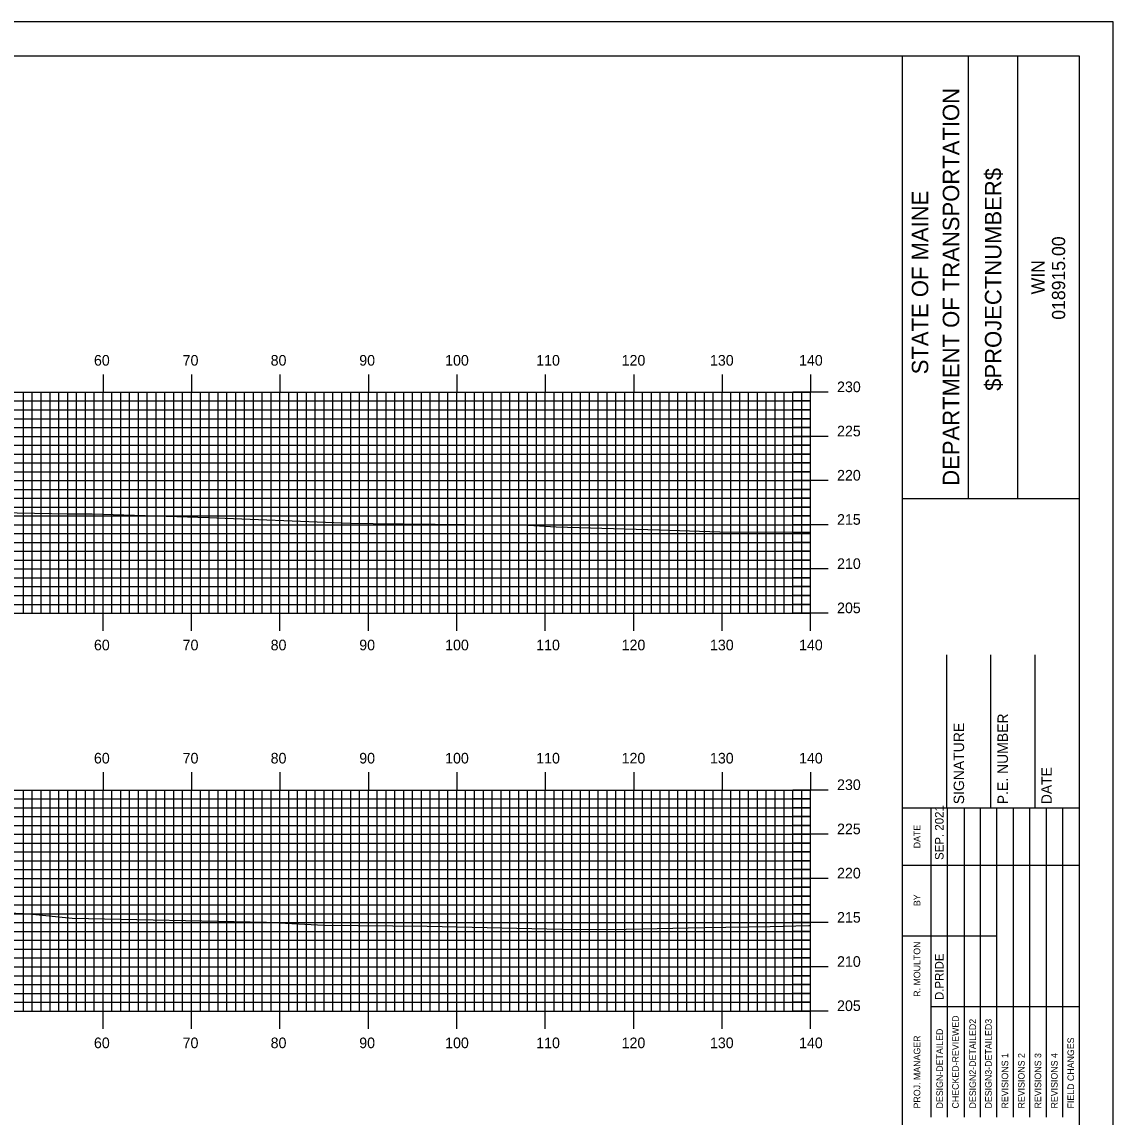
# Model space of a CAD drawing. Extents: x 1819637 to 1819981, y 442591 to 442811.
# Drawn here: x 1819854 to 1819977.4, y 442686.7 to 442810.5 of the extents above; entities that cross this region are included whole.
import ezdxf

# ---------------------------------------------------------------- set-up
doc = ezdxf.new("R2010")
doc.units = 0
for name, color, linetype in [('BORDER', 7, 'Continuous'), ('H_V ANNOTATION', 7, 'Continuous'), ('MAJOR', 7, 'Continuous'), ('MINOR', 7, 'Continuous'), ('PLOT BOUNDARY', 7, 'Continuous'), ('S_Roadway_Centerline', 7, 'Continuous')]:
    doc.layers.add(name, color=color, linetype=linetype)

msp = doc.modelspace()

# ---------------------------------------------------------------- linework, layer by layer
at = {"layer": 'BORDER'}
for p, q in [((1819953.58, 442596.67), (1819953.58, 442806.67)), ((1819961.03, 442756.66), (1819961.03, 442806.66)), ((1819966.62, 442756.66), (1819966.62, 442806.66)), ((1819953.58, 442756.65), (1819973.58, 442756.65)), ((1819958.58, 442721.67), (1819958.58, 442738.97)), ((1819963.58, 442721.67), (1819963.58, 442738.97)), ((1819968.58, 442721.67), (1819968.58, 442738.97)), ((1819953.58, 442721.67), (1819973.58, 442721.67))]:
    msp.add_line(p, q, dxfattribs=at)
msp.add_lwpolyline([(1819653.58, 442596.67), (1819973.58, 442596.67), (1819973.58, 442806.67), (1819653.58, 442806.67)], close=True, dxfattribs=at)
for points in [[(1819956.81, 442715.17), (1819956.81, 442721.67)], [(1819958.67, 442686.68), (1819958.67, 442721.67)], [(1819960.54, 442721.67), (1819960.54, 442686.68)], [(1819962.4, 442686.68), (1819962.4, 442721.67)], [(1819964.26, 442686.68), (1819964.26, 442721.67)], [(1819966.13, 442686.68), (1819966.13, 442721.67)], [(1819967.99, 442686.68), (1819967.99, 442721.67)], [(1819969.85, 442686.68), (1819969.85, 442721.67)], [(1819971.72, 442686.68), (1819971.72, 442721.67)], [(1819956.81, 442686.68), (1819956.81, 442720.26)], [(1819953.58, 442715.17), (1819973.58, 442715.17)], [(1819953.58, 442707.17), (1819956.81, 442707.17)], [(1819956.81, 442707.17), (1819964.26, 442707.17)], [(1819956.81, 442699.17), (1819973.58, 442699.17)]]:
    msp.add_lwpolyline(points, dxfattribs=at)
at = {"layer": 'MAJOR'}
for p, q in [((1819863.18, 442770.67), (1819863.18, 442768.67)), ((1819873.18, 442770.67), (1819873.18, 442768.67)), ((1819883.18, 442770.67), (1819883.18, 442768.67)), ((1819893.18, 442770.67), (1819893.18, 442768.67)), ((1819903.18, 442770.67), (1819903.18, 442768.67)), ((1819913.18, 442770.67), (1819913.18, 442768.67)), ((1819923.18, 442770.67), (1819923.18, 442768.67)), ((1819933.18, 442770.67), (1819933.18, 442768.67)), ((1819943.18, 442770.67), (1819943.18, 442768.67)), ((1819663.18, 442768.67), (1819943.18, 442768.67)), ((1819663.18, 442768.67), (1819943.18, 442768.67)), ((1819863.18, 442743.67), (1819863.18, 442768.67)), ((1819873.18, 442743.67), (1819873.18, 442768.67)), ((1819883.18, 442743.67), (1819883.18, 442768.67)), ((1819893.18, 442743.67), (1819893.18, 442768.67)), ((1819903.18, 442743.67), (1819903.18, 442768.67)), ((1819913.18, 442743.67), (1819913.18, 442768.67)), ((1819923.18, 442743.67), (1819923.18, 442768.67)), ((1819933.18, 442743.67), (1819933.18, 442768.67)), ((1819945.18, 442768.67), (1819941.17, 442768.67)), ((1819943.18, 442743.67), (1819943.18, 442768.67)), ((1819943.18, 442743.67), (1819943.18, 442768.67)), ((1819663.18, 442763.67), (1819943.18, 442763.67)), ((1819945.18, 442763.67), (1819941.17, 442763.67)), ((1819663.18, 442758.67), (1819943.18, 442758.67)), ((1819945.18, 442758.67), (1819941.17, 442758.67)), ((1819663.18, 442753.67), (1819943.18, 442753.67)), ((1819945.18, 442753.67), (1819941.17, 442753.67)), ((1819663.18, 442748.67), (1819943.18, 442748.67)), ((1819945.18, 442748.67), (1819941.17, 442748.67)), ((1819663.18, 442743.67), (1819943.18, 442743.67)), ((1819663.18, 442743.67), (1819943.18, 442743.67)), ((1819863.18, 442741.66), (1819863.18, 442743.67)), ((1819873.18, 442741.66), (1819873.18, 442743.67)), ((1819883.18, 442741.66), (1819883.18, 442743.67)), ((1819893.18, 442741.66), (1819893.18, 442743.67)), ((1819903.18, 442741.66), (1819903.18, 442743.67)), ((1819913.18, 442741.66), (1819913.18, 442743.67)), ((1819923.18, 442741.66), (1819923.18, 442743.67)), ((1819933.18, 442741.66), (1819933.18, 442743.67)), ((1819945.18, 442743.67), (1819941.17, 442743.67)), ((1819943.18, 442741.66), (1819943.18, 442743.67)), ((1819863.18, 442725.67), (1819863.18, 442723.67)), ((1819873.18, 442725.67), (1819873.18, 442723.67)), ((1819883.18, 442725.67), (1819883.18, 442723.67)), ((1819893.18, 442725.67), (1819893.18, 442723.67)), ((1819903.18, 442725.67), (1819903.18, 442723.67)), ((1819913.18, 442725.67), (1819913.18, 442723.67)), ((1819923.18, 442725.67), (1819923.18, 442723.67)), ((1819933.18, 442725.67), (1819933.18, 442723.67)), ((1819943.18, 442725.67), (1819943.18, 442723.67)), ((1819663.18, 442723.67), (1819943.18, 442723.67)), ((1819663.18, 442723.67), (1819943.18, 442723.67)), ((1819863.18, 442698.67), (1819863.18, 442723.67)), ((1819873.18, 442698.67), (1819873.18, 442723.67)), ((1819883.18, 442698.67), (1819883.18, 442723.67)), ((1819893.18, 442698.67), (1819893.18, 442723.67)), ((1819903.18, 442698.67), (1819903.18, 442723.67)), ((1819913.18, 442698.67), (1819913.18, 442723.67)), ((1819923.18, 442698.67), (1819923.18, 442723.67)), ((1819933.18, 442698.67), (1819933.18, 442723.67)), ((1819945.18, 442723.67), (1819941.17, 442723.67)), ((1819943.18, 442698.67), (1819943.18, 442723.67)), ((1819943.18, 442698.67), (1819943.18, 442723.67)), ((1819663.18, 442718.67), (1819943.18, 442718.67)), ((1819945.18, 442718.67), (1819941.17, 442718.67)), ((1819663.18, 442713.67), (1819943.18, 442713.67)), ((1819945.18, 442713.67), (1819941.17, 442713.67)), ((1819663.18, 442708.67), (1819943.18, 442708.67)), ((1819945.18, 442708.67), (1819941.17, 442708.67)), ((1819663.18, 442703.67), (1819943.18, 442703.67)), ((1819945.18, 442703.67), (1819941.17, 442703.67)), ((1819663.18, 442698.67), (1819943.18, 442698.67)), ((1819663.18, 442698.67), (1819943.18, 442698.67)), ((1819863.18, 442696.66), (1819863.18, 442698.67)), ((1819873.18, 442696.66), (1819873.18, 442698.67)), ((1819883.18, 442696.66), (1819883.18, 442698.67)), ((1819893.18, 442696.66), (1819893.18, 442698.67)), ((1819903.18, 442696.66), (1819903.18, 442698.67)), ((1819913.18, 442696.66), (1819913.18, 442698.67)), ((1819923.18, 442696.66), (1819923.18, 442698.67)), ((1819933.18, 442696.66), (1819933.18, 442698.67)), ((1819945.18, 442698.67), (1819941.17, 442698.67)), ((1819943.18, 442696.66), (1819943.18, 442698.67))]:
    msp.add_line(p, q, dxfattribs=at)
at = {"layer": 'MINOR'}
for p, q in [((1819854.18, 442743.67), (1819854.18, 442768.67)), ((1819855.18, 442743.67), (1819855.18, 442768.67)), ((1819856.18, 442743.67), (1819856.18, 442768.67)), ((1819857.18, 442743.67), (1819857.18, 442768.67)), ((1819858.18, 442743.67), (1819858.18, 442768.67)), ((1819859.18, 442743.67), (1819859.18, 442768.67)), ((1819860.18, 442743.67), (1819860.18, 442768.67)), ((1819861.18, 442743.67), (1819861.18, 442768.67)), ((1819862.18, 442743.67), (1819862.18, 442768.67)), ((1819864.18, 442743.67), (1819864.18, 442768.67)), ((1819865.18, 442743.67), (1819865.18, 442768.67)), ((1819866.18, 442743.67), (1819866.18, 442768.67)), ((1819867.18, 442743.67), (1819867.18, 442768.67)), ((1819868.18, 442743.67), (1819868.18, 442768.67)), ((1819869.18, 442743.67), (1819869.18, 442768.67)), ((1819870.18, 442743.67), (1819870.18, 442768.67)), ((1819871.18, 442743.67), (1819871.18, 442768.67)), ((1819872.18, 442743.67), (1819872.18, 442768.67)), ((1819874.18, 442743.67), (1819874.18, 442768.67)), ((1819875.18, 442743.67), (1819875.18, 442768.67)), ((1819876.18, 442743.67), (1819876.18, 442768.67)), ((1819877.18, 442743.67), (1819877.18, 442768.67)), ((1819878.18, 442743.67), (1819878.18, 442768.67)), ((1819879.18, 442743.67), (1819879.18, 442768.67)), ((1819880.18, 442743.67), (1819880.18, 442768.67)), ((1819881.18, 442743.67), (1819881.18, 442768.67)), ((1819882.18, 442743.67), (1819882.18, 442768.67)), ((1819884.18, 442743.67), (1819884.18, 442768.67)), ((1819885.18, 442743.67), (1819885.18, 442768.67)), ((1819886.18, 442743.67), (1819886.18, 442768.67)), ((1819887.18, 442743.67), (1819887.18, 442768.67)), ((1819888.18, 442743.67), (1819888.18, 442768.67)), ((1819889.18, 442743.67), (1819889.18, 442768.67)), ((1819890.18, 442743.67), (1819890.18, 442768.67)), ((1819891.18, 442743.67), (1819891.18, 442768.67)), ((1819892.18, 442743.67), (1819892.18, 442768.67)), ((1819894.18, 442743.67), (1819894.18, 442768.67)), ((1819895.18, 442743.67), (1819895.18, 442768.67)), ((1819896.18, 442743.67), (1819896.18, 442768.67)), ((1819897.18, 442743.67), (1819897.18, 442768.67)), ((1819898.18, 442743.67), (1819898.18, 442768.67)), ((1819899.18, 442743.67), (1819899.18, 442768.67)), ((1819900.18, 442743.67), (1819900.18, 442768.67)), ((1819901.18, 442743.67), (1819901.18, 442768.67)), ((1819902.18, 442743.67), (1819902.18, 442768.67)), ((1819904.18, 442743.67), (1819904.18, 442768.67)), ((1819905.18, 442743.67), (1819905.18, 442768.67)), ((1819906.18, 442743.67), (1819906.18, 442768.67)), ((1819907.18, 442743.67), (1819907.18, 442768.67)), ((1819908.18, 442743.67), (1819908.18, 442768.67)), ((1819909.18, 442743.67), (1819909.18, 442768.67)), ((1819910.18, 442743.67), (1819910.18, 442768.67)), ((1819911.18, 442743.67), (1819911.18, 442768.67)), ((1819912.18, 442743.67), (1819912.18, 442768.67)), ((1819914.18, 442743.67), (1819914.18, 442768.67)), ((1819915.18, 442743.67), (1819915.18, 442768.67)), ((1819916.18, 442743.67), (1819916.18, 442768.67)), ((1819917.18, 442743.67), (1819917.18, 442768.67)), ((1819918.18, 442743.67), (1819918.18, 442768.67)), ((1819919.18, 442743.67), (1819919.18, 442768.67)), ((1819920.18, 442743.67), (1819920.18, 442768.67)), ((1819921.18, 442743.67), (1819921.18, 442768.67)), ((1819922.18, 442743.67), (1819922.18, 442768.67)), ((1819924.18, 442743.67), (1819924.18, 442768.67)), ((1819925.18, 442743.67), (1819925.18, 442768.67)), ((1819926.18, 442743.67), (1819926.18, 442768.67)), ((1819927.18, 442743.67), (1819927.18, 442768.67)), ((1819928.18, 442743.67), (1819928.18, 442768.67)), ((1819929.18, 442743.67), (1819929.18, 442768.67)), ((1819930.18, 442743.67), (1819930.18, 442768.67)), ((1819931.18, 442743.67), (1819931.18, 442768.67)), ((1819932.18, 442743.67), (1819932.18, 442768.67)), ((1819934.18, 442743.67), (1819934.18, 442768.67)), ((1819935.18, 442743.67), (1819935.18, 442768.67)), ((1819936.18, 442743.67), (1819936.18, 442768.67)), ((1819937.18, 442743.67), (1819937.18, 442768.67)), ((1819938.18, 442743.67), (1819938.18, 442768.67)), ((1819939.18, 442743.67), (1819939.18, 442768.67)), ((1819940.18, 442743.67), (1819940.18, 442768.67)), ((1819941.18, 442743.67), (1819941.18, 442768.67)), ((1819942.18, 442743.67), (1819942.18, 442768.67)), ((1819663.18, 442767.67), (1819943.18, 442767.67)), ((1819943.18, 442767.67), (1819941.17, 442767.67)), ((1819663.18, 442766.67), (1819943.18, 442766.67)), ((1819943.18, 442766.67), (1819941.17, 442766.67)), ((1819663.18, 442765.67), (1819943.18, 442765.67)), ((1819943.18, 442765.67), (1819941.17, 442765.67)), ((1819663.18, 442764.67), (1819943.18, 442764.67)), ((1819943.18, 442764.67), (1819941.17, 442764.67)), ((1819663.18, 442762.67), (1819943.18, 442762.67)), ((1819943.18, 442762.67), (1819941.17, 442762.67)), ((1819663.18, 442761.67), (1819943.18, 442761.67)), ((1819943.18, 442761.67), (1819941.17, 442761.67)), ((1819663.18, 442760.67), (1819943.18, 442760.67)), ((1819943.18, 442760.67), (1819941.17, 442760.67)), ((1819663.18, 442759.67), (1819943.18, 442759.67)), ((1819943.18, 442759.67), (1819941.17, 442759.67)), ((1819663.18, 442757.67), (1819943.18, 442757.67)), ((1819943.18, 442757.67), (1819941.17, 442757.67)), ((1819663.18, 442756.67), (1819943.18, 442756.67)), ((1819943.18, 442756.67), (1819941.17, 442756.67)), ((1819663.18, 442755.67), (1819943.18, 442755.67)), ((1819943.18, 442755.67), (1819941.17, 442755.67)), ((1819663.18, 442754.67), (1819943.18, 442754.67)), ((1819943.18, 442754.67), (1819941.17, 442754.67)), ((1819663.18, 442752.67), (1819943.18, 442752.67)), ((1819943.18, 442752.67), (1819941.17, 442752.67)), ((1819663.18, 442751.67), (1819943.18, 442751.67)), ((1819943.18, 442751.67), (1819941.17, 442751.67)), ((1819663.18, 442750.67), (1819943.18, 442750.67)), ((1819943.18, 442750.67), (1819941.17, 442750.67)), ((1819663.18, 442749.67), (1819943.18, 442749.67)), ((1819943.18, 442749.67), (1819941.17, 442749.67)), ((1819663.18, 442747.67), (1819943.18, 442747.67)), ((1819943.18, 442747.67), (1819941.17, 442747.67)), ((1819663.18, 442746.67), (1819943.18, 442746.67)), ((1819943.18, 442746.67), (1819941.17, 442746.67)), ((1819663.18, 442745.67), (1819943.18, 442745.67)), ((1819943.18, 442745.67), (1819941.17, 442745.67)), ((1819663.18, 442744.67), (1819943.18, 442744.67)), ((1819943.18, 442744.67), (1819941.17, 442744.67)), ((1819854.18, 442698.67), (1819854.18, 442723.67)), ((1819855.18, 442698.67), (1819855.18, 442723.67)), ((1819856.18, 442698.67), (1819856.18, 442723.67)), ((1819857.18, 442698.67), (1819857.18, 442723.67)), ((1819858.18, 442698.67), (1819858.18, 442723.67)), ((1819859.18, 442698.67), (1819859.18, 442723.67)), ((1819860.18, 442698.67), (1819860.18, 442723.67)), ((1819861.18, 442698.67), (1819861.18, 442723.67)), ((1819862.18, 442698.67), (1819862.18, 442723.67)), ((1819864.18, 442698.67), (1819864.18, 442723.67)), ((1819865.18, 442698.67), (1819865.18, 442723.67)), ((1819866.18, 442698.67), (1819866.18, 442723.67)), ((1819867.18, 442698.67), (1819867.18, 442723.67)), ((1819868.18, 442698.67), (1819868.18, 442723.67)), ((1819869.18, 442698.67), (1819869.18, 442723.67)), ((1819870.18, 442698.67), (1819870.18, 442723.67)), ((1819871.18, 442698.67), (1819871.18, 442723.67)), ((1819872.18, 442698.67), (1819872.18, 442723.67)), ((1819874.18, 442698.67), (1819874.18, 442723.67)), ((1819875.18, 442698.67), (1819875.18, 442723.67)), ((1819876.18, 442698.67), (1819876.18, 442723.67)), ((1819877.18, 442698.67), (1819877.18, 442723.67)), ((1819878.18, 442698.67), (1819878.18, 442723.67)), ((1819879.18, 442698.67), (1819879.18, 442723.67)), ((1819880.18, 442698.67), (1819880.18, 442723.67)), ((1819881.18, 442698.67), (1819881.18, 442723.67)), ((1819882.18, 442698.67), (1819882.18, 442723.67)), ((1819884.18, 442698.67), (1819884.18, 442723.67)), ((1819885.18, 442698.67), (1819885.18, 442723.67)), ((1819886.18, 442698.67), (1819886.18, 442723.67)), ((1819887.18, 442698.67), (1819887.18, 442723.67)), ((1819888.18, 442698.67), (1819888.18, 442723.67)), ((1819889.18, 442698.67), (1819889.18, 442723.67)), ((1819890.18, 442698.67), (1819890.18, 442723.67)), ((1819891.18, 442698.67), (1819891.18, 442723.67)), ((1819892.18, 442698.67), (1819892.18, 442723.67)), ((1819894.18, 442698.67), (1819894.18, 442723.67)), ((1819895.18, 442698.67), (1819895.18, 442723.67)), ((1819896.18, 442698.67), (1819896.18, 442723.67)), ((1819897.18, 442698.67), (1819897.18, 442723.67)), ((1819898.18, 442698.67), (1819898.18, 442723.67)), ((1819899.18, 442698.67), (1819899.18, 442723.67)), ((1819900.18, 442698.67), (1819900.18, 442723.67)), ((1819901.18, 442698.67), (1819901.18, 442723.67)), ((1819902.18, 442698.67), (1819902.18, 442723.67)), ((1819904.18, 442698.67), (1819904.18, 442723.67)), ((1819905.18, 442698.67), (1819905.18, 442723.67)), ((1819906.18, 442698.67), (1819906.18, 442723.67)), ((1819907.18, 442698.67), (1819907.18, 442723.67)), ((1819908.18, 442698.67), (1819908.18, 442723.67)), ((1819909.18, 442698.67), (1819909.18, 442723.67)), ((1819910.18, 442698.67), (1819910.18, 442723.67)), ((1819911.18, 442698.67), (1819911.18, 442723.67)), ((1819912.18, 442698.67), (1819912.18, 442723.67)), ((1819914.18, 442698.67), (1819914.18, 442723.67)), ((1819915.18, 442698.67), (1819915.18, 442723.67)), ((1819916.18, 442698.67), (1819916.18, 442723.67)), ((1819917.18, 442698.67), (1819917.18, 442723.67)), ((1819918.18, 442698.67), (1819918.18, 442723.67)), ((1819919.18, 442698.67), (1819919.18, 442723.67)), ((1819920.18, 442698.67), (1819920.18, 442723.67)), ((1819921.18, 442698.67), (1819921.18, 442723.67)), ((1819922.18, 442698.67), (1819922.18, 442723.67)), ((1819924.18, 442698.67), (1819924.18, 442723.67)), ((1819925.18, 442698.67), (1819925.18, 442723.67)), ((1819926.18, 442698.67), (1819926.18, 442723.67)), ((1819927.18, 442698.67), (1819927.18, 442723.67)), ((1819928.18, 442698.67), (1819928.18, 442723.67)), ((1819929.18, 442698.67), (1819929.18, 442723.67)), ((1819930.18, 442698.67), (1819930.18, 442723.67)), ((1819931.18, 442698.67), (1819931.18, 442723.67)), ((1819932.18, 442698.67), (1819932.18, 442723.67)), ((1819934.18, 442698.67), (1819934.18, 442723.67)), ((1819935.18, 442698.67), (1819935.18, 442723.67)), ((1819936.18, 442698.67), (1819936.18, 442723.67)), ((1819937.18, 442698.67), (1819937.18, 442723.67)), ((1819938.18, 442698.67), (1819938.18, 442723.67)), ((1819939.18, 442698.67), (1819939.18, 442723.67)), ((1819940.18, 442698.67), (1819940.18, 442723.67)), ((1819941.18, 442698.67), (1819941.18, 442723.67)), ((1819942.18, 442698.67), (1819942.18, 442723.67)), ((1819663.18, 442722.67), (1819943.18, 442722.67)), ((1819663.18, 442721.67), (1819943.18, 442721.67)), ((1819943.18, 442722.67), (1819941.17, 442722.67)), ((1819943.18, 442721.67), (1819941.17, 442721.67)), ((1819663.18, 442720.67), (1819943.18, 442720.67)), ((1819943.18, 442720.67), (1819941.17, 442720.67)), ((1819663.18, 442719.67), (1819943.18, 442719.67)), ((1819943.18, 442719.67), (1819941.17, 442719.67)), ((1819663.18, 442717.67), (1819943.18, 442717.67)), ((1819663.18, 442716.67), (1819943.18, 442716.67)), ((1819943.18, 442717.67), (1819941.17, 442717.67)), ((1819943.18, 442716.67), (1819941.17, 442716.67)), ((1819663.18, 442715.67), (1819943.18, 442715.67)), ((1819943.18, 442715.67), (1819941.17, 442715.67)), ((1819663.18, 442714.67), (1819943.18, 442714.67)), ((1819943.18, 442714.67), (1819941.17, 442714.67)), ((1819663.18, 442712.67), (1819943.18, 442712.67)), ((1819663.18, 442711.67), (1819943.18, 442711.67)), ((1819943.18, 442712.67), (1819941.17, 442712.67)), ((1819943.18, 442711.67), (1819941.17, 442711.67)), ((1819663.18, 442710.67), (1819943.18, 442710.67)), ((1819943.18, 442710.67), (1819941.17, 442710.67)), ((1819663.18, 442709.67), (1819943.18, 442709.67)), ((1819943.18, 442709.67), (1819941.17, 442709.67)), ((1819663.18, 442707.67), (1819943.18, 442707.67)), ((1819663.18, 442706.67), (1819943.18, 442706.67)), ((1819943.18, 442707.67), (1819941.17, 442707.67)), ((1819943.18, 442706.67), (1819941.17, 442706.67)), ((1819663.18, 442705.67), (1819943.18, 442705.67)), ((1819943.18, 442705.67), (1819941.17, 442705.67)), ((1819663.18, 442704.67), (1819943.18, 442704.67)), ((1819943.18, 442704.67), (1819941.17, 442704.67)), ((1819663.18, 442702.67), (1819943.18, 442702.67)), ((1819663.18, 442701.67), (1819943.18, 442701.67)), ((1819943.18, 442702.67), (1819941.17, 442702.67)), ((1819943.18, 442701.67), (1819941.17, 442701.67)), ((1819663.18, 442700.67), (1819943.18, 442700.67)), ((1819943.18, 442700.67), (1819941.17, 442700.67)), ((1819663.18, 442699.67), (1819943.18, 442699.67)), ((1819943.18, 442699.67), (1819941.17, 442699.67))]:
    msp.add_line(p, q, dxfattribs=at)
at = {"layer": 'PLOT BOUNDARY'}
msp.add_lwpolyline([(1819637.39, 442590.55), (1819977.39, 442590.55), (1819977.39, 442810.55), (1819637.39, 442810.55)], close=True, dxfattribs=at)
at = {"layer": 'S_Roadway_Centerline'}
for points in [[(1819841.85, 442755.26), (1819859.26, 442754.92), (1819861.96, 442754.91), (1819875.12, 442754.49), (1819890.2, 442753.89), (1819891.11, 442753.86), (1819893.74, 442753.82), (1819911.24, 442753.63), (1819914.4, 442753.43), (1819926.06, 442753.09), (1819932.93, 442752.88), (1819942.67, 442752.85), (1819943.18, 442752.86)], [(1819849.54, 442709.93), (1819854.82, 442709.66), (1819859.69, 442709.17), (1819881.65, 442708.74), (1819888.14, 442708.37), (1819899.81, 442708.27), (1819916.75, 442707.89), (1819922.32, 442707.93), (1819931.13, 442708.12), (1819938.6, 442708.25), (1819942.99, 442708.33), (1819943.18, 442708.35)]]:
    msp.add_lwpolyline(points, dxfattribs=at)

# ---------------------------------------------------------------- texts
at = {"layer": 'BORDER'}
for s, height, p in [('DEPARTMENT OF TRANSPORTATION', 1.8635, (1819959.99, 442758.08)), ('$PROJECTNUMBER$', 1.8635, (1819964.76, 442768.82)), ('STATE OF MAINE', 1.8635, (1819956.49, 442770.69)), ('018915.00', 1.491, (1819971.97, 442776.86)), ('WIN', 1.491, (1819969.65, 442779.73)), ('P.E. NUMBER', 1.1811, (1819965.5, 442722.06)), ('SIGNATURE', 1.181, (1819960.54, 442722.06)), ('DATE', 1.181, (1819970.46, 442722.06)), ('SEP. 2021', 0.969, (1819958.22, 442715.76)), ('DATE', 0.743, (1819955.59, 442717.08)), ('BY', 0.743, (1819955.59, 442710.54)), ('R. MOULTON', 0.745, (1819955.59, 442700.28)), ('D.PRIDE', 0.969, (1819958.22, 442699.92)), ('CHECKED-REVIEWED', 0.7455, (1819959.94, 442687.65)), ('DESIGN2-DETAILED2', 0.7455, (1819961.88, 442687.65)), ('DESIGN3-DETAILED3', 0.7455, (1819963.67, 442687.65)), ('PROJ. MANAGER', 0.7455, (1819955.59, 442687.65)), ('DESIGN-DETAILED', 0.7455, (1819958.15, 442687.65)), ('FIELD CHANGES', 0.7455, (1819972.98, 442687.65)), ('REVISIONS 1', 0.7455, (1819965.53, 442687.65)), ('REVISIONS 2', 0.7455, (1819967.39, 442687.65)), ('REVISIONS 3', 0.7455, (1819969.26, 442687.65)), ('REVISIONS 4', 0.7455, (1819971.12, 442687.65))]:
    msp.add_text(s, height=height, rotation=90, dxfattribs=at).set_placement(p)
at = {"layer": 'H_V ANNOTATION'}
for s, p in [('60', (1819862.15, 442771.67)), ('70', (1819872.18, 442771.67)), ('80', (1819882.13, 442771.67)), ('90', (1819892.15, 442771.67)), ('100', (1819901.86, 442771.67)), ('110', (1819912.16, 442771.67)), ('120', (1819921.82, 442771.67)), ('130', (1819931.81, 442771.67)), ('140', (1819941.88, 442771.67)), ('230', (1819946.18, 442768.67)), ('225', (1819946.18, 442763.67)), ('220', (1819946.18, 442758.67)), ('215', (1819946.18, 442753.67)), ('210', (1819946.18, 442748.67)), ('205', (1819946.18, 442743.67)), ('60', (1819862.15, 442739.47)), ('70', (1819872.18, 442739.47)), ('80', (1819882.13, 442739.47)), ('90', (1819892.15, 442739.47)), ('100', (1819901.86, 442739.47)), ('110', (1819912.16, 442739.47)), ('120', (1819921.82, 442739.47)), ('130', (1819931.81, 442739.47)), ('140', (1819941.88, 442739.47)), ('60', (1819862.15, 442726.67)), ('70', (1819872.18, 442726.67)), ('80', (1819882.13, 442726.67)), ('90', (1819892.15, 442726.67)), ('100', (1819901.86, 442726.67)), ('110', (1819912.16, 442726.67)), ('120', (1819921.82, 442726.67)), ('130', (1819931.81, 442726.67)), ('140', (1819941.88, 442726.67)), ('230', (1819946.18, 442723.67)), ('225', (1819946.18, 442718.67)), ('220', (1819946.18, 442713.67)), ('215', (1819946.18, 442708.67)), ('210', (1819946.18, 442703.67)), ('205', (1819946.18, 442698.67)), ('60', (1819862.15, 442694.47)), ('70', (1819872.18, 442694.47)), ('80', (1819882.13, 442694.47)), ('90', (1819892.15, 442694.47)), ('100', (1819901.86, 442694.47)), ('110', (1819912.16, 442694.47)), ('120', (1819921.82, 442694.47)), ('130', (1819931.81, 442694.47)), ('140', (1819941.88, 442694.47))]:
    msp.add_text(s, height=1.2, dxfattribs=at).set_placement(p)

doc.saveas('drawing.dxf')
